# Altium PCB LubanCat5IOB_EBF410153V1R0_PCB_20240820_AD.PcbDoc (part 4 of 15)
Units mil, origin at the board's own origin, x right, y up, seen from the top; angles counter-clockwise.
Board outline 6811.02 x 4055.12 mil, 6 copper layers (TOP, GND02, ART03, ART04, PWR05, BOTTOM), stack 59.279 mil thick; 981 components, 783 nets, 3627 pads, 2669 vias.
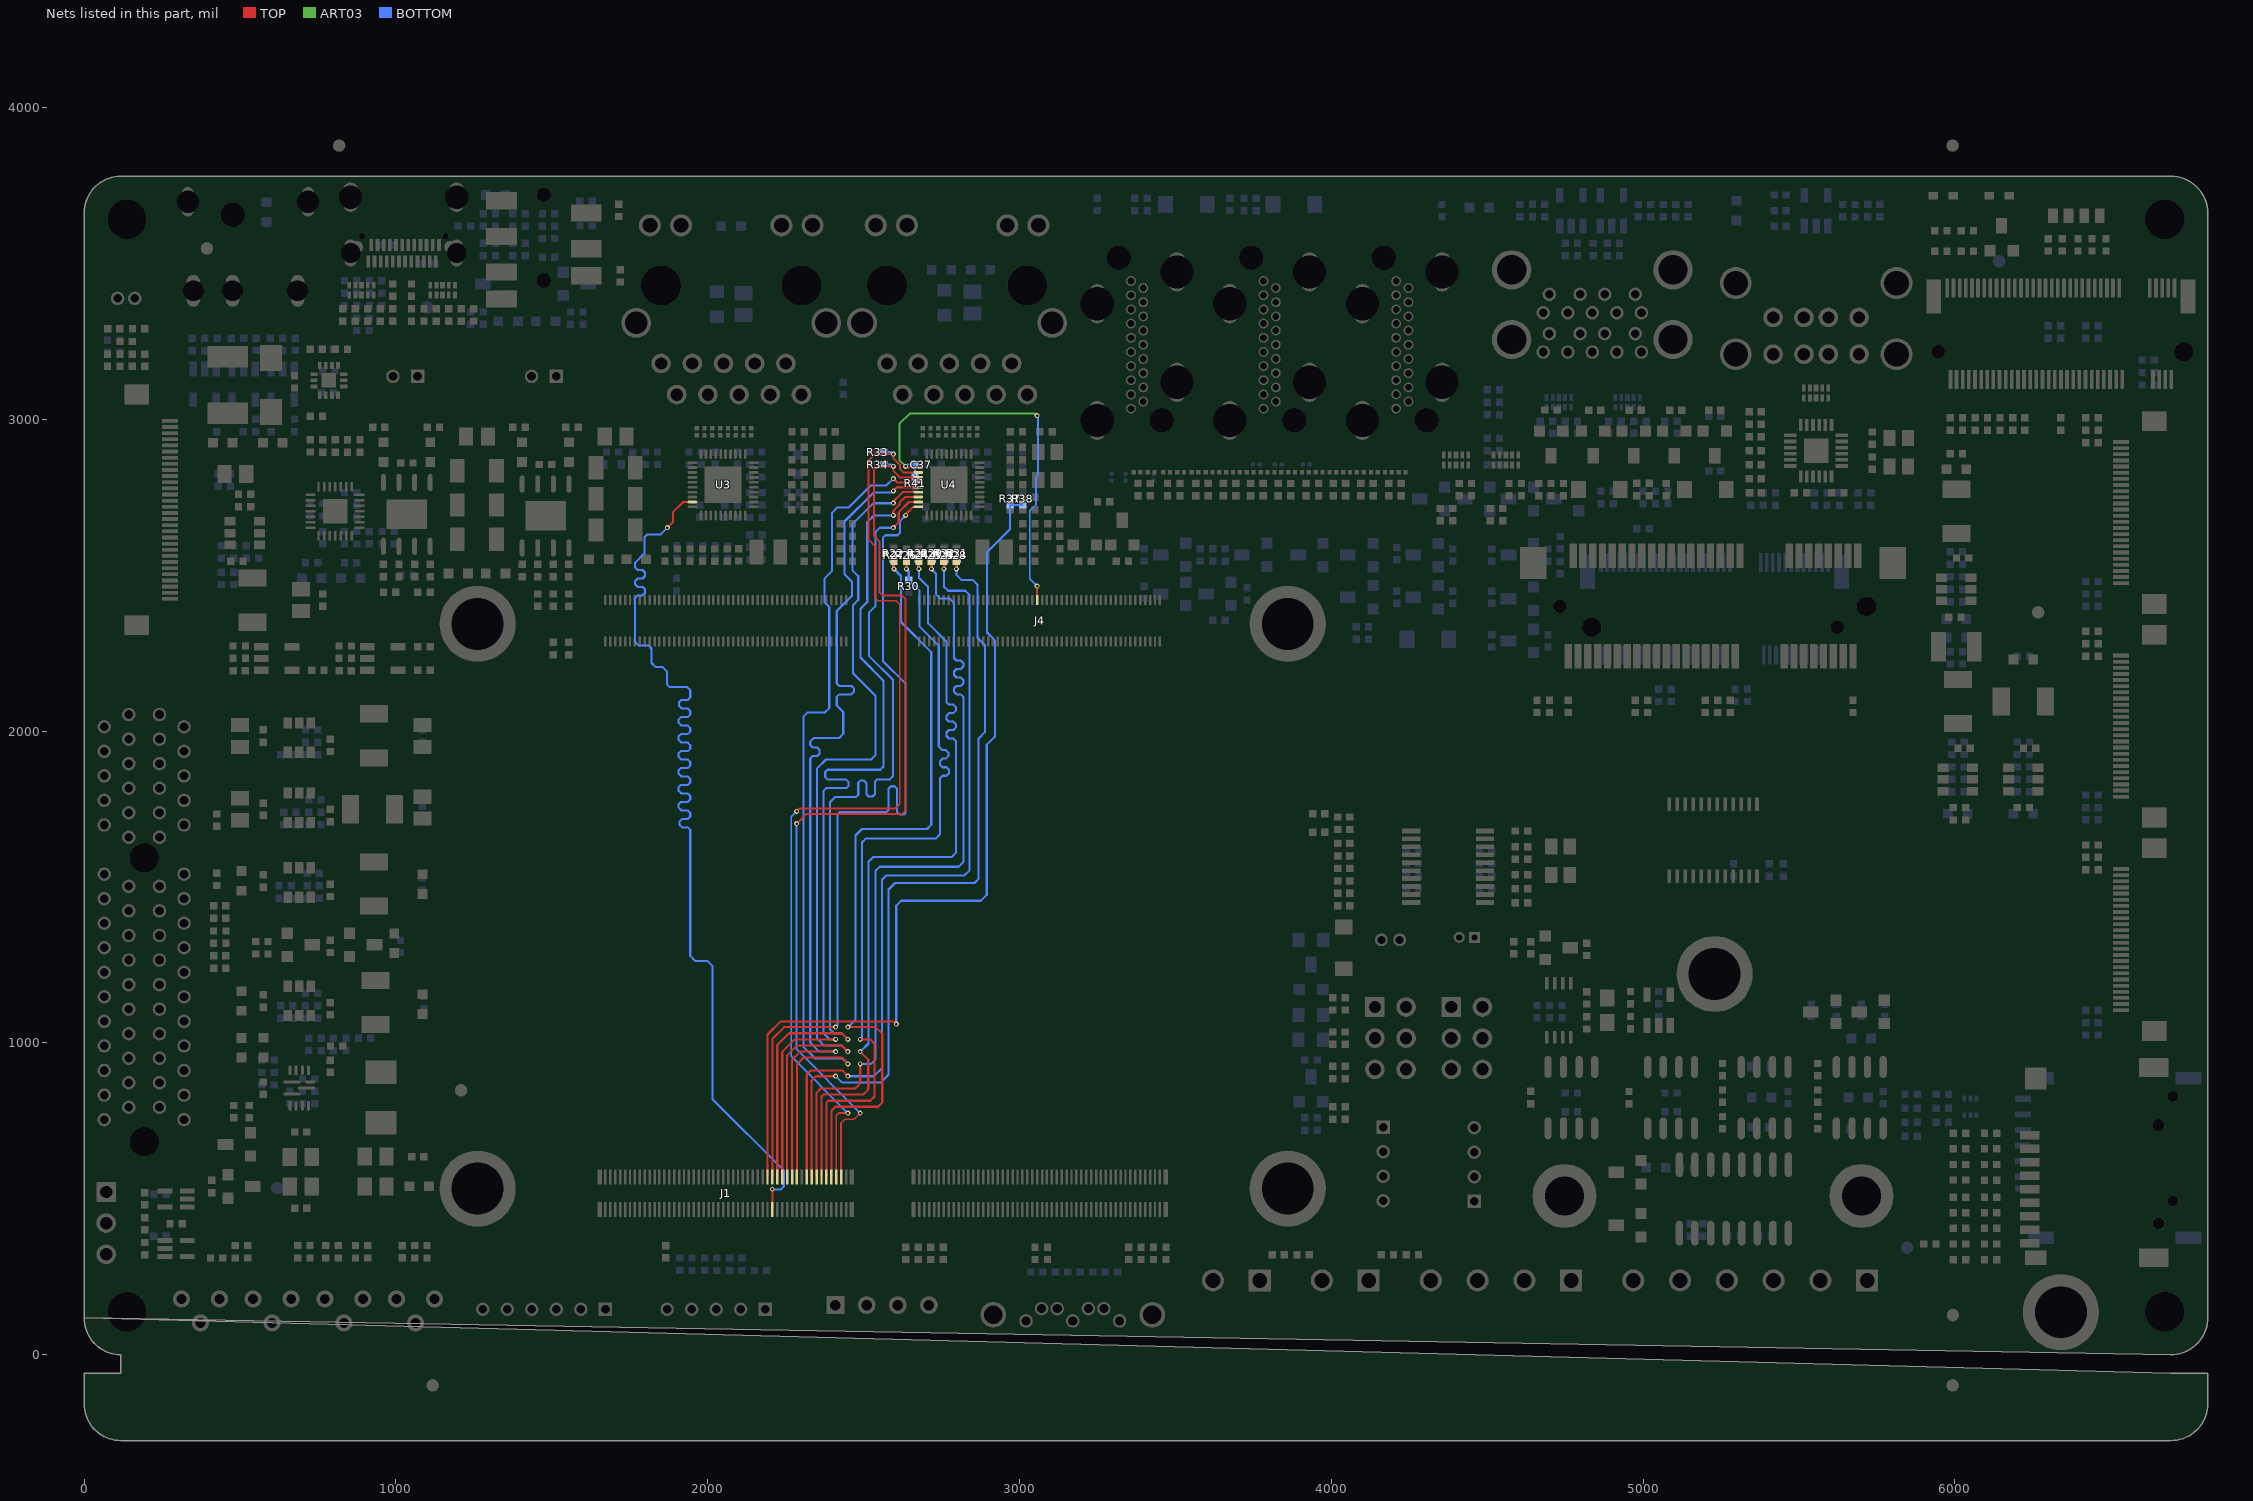
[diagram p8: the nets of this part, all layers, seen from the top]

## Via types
v1: diameter 16, hole 8, TOP to BOTTOM, 2357 vias
v2: diameter 14, hole 8, TOP to BOTTOM, 308 vias
v3: diameter 20, hole 10, TOP to BOTTOM, 4 vias

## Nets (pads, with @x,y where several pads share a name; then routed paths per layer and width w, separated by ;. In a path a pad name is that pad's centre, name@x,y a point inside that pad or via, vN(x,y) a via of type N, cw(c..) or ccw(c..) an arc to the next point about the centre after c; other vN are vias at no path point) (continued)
GMAC0_TXEN: J1.70 U3.19 | length 3227.8
  TOP w6.8: v1(1870.85,2652.2) 1888.25,2669.6 1888.25,2701.66 1921.47,2734.88 U3.19@1951.16,2734.88 ; J1.70@2207.58,465.62 v2(2207.58,530)
  BOTTOM w6.8: v1(1870.85,2652.2) 1849.51,2630.86 1807,2630.86 1797,2620.86 1797,2570 1767.39,2540.39 1767.39,2524.69 1775.35,2516.72 1791.03,2516.72 1799,2508.75 1799,2497.49 1791.03,2489.52 1775.35,2489.52 1767.39,2481.55 1767.39,2470.29 1775.35,2462.32 1791.03,2462.32 1799,2454.35 1799,2443.09 1791.03,2435.12 1775.35,2435.12 1767.39,2427.15 1767.39,2285.61 1779,2274 1811,2274 1820,2265 1820,2218.6 1833.6,2205 1855.4,2205 1869,2191.4 1869,2150 1878,2141 1935,2141 1944,2132 1944,2107.53 1936.03,2099.57 1914.97,2099.57 1908,2092.6 1908,2081.33 1916.97,2072.37 1936.03,2072.37 1944,2064.4 1944,2052.6 1936.03,2044.63 1913.97,2044.63 1907,2037.67 1907,2026.4 1915.97,2017.43 1936.03,2017.43 1944,2009.47 1944,1998.2 1936.03,1990.23 1913.97,1990.23 1907,1983.27 1907,1972 1915.97,1963.03 1936.03,1963.03 1944,1955.07 1944,1943.8 1936.03,1935.83 1913.97,1935.83 1907,1928.87 1907,1917.6 1915.97,1908.63 1936.03,1908.63 1944,1900.67 1944,1889.4 1936.03,1881.43 1913.97,1881.43 1907,1874.47 1907,1863.2 1915.97,1854.23 1936.03,1854.23 1944,1846.27 1944,1835 1936.03,1827.03 1913.97,1827.03 1907,1820.07 1907,1808.8 1915.97,1799.83 1936.03,1799.83 1944,1791.87 1944,1780.6 1936.03,1772.63 1913.97,1772.63 1907,1765.67 1907,1754.4 1915.97,1745.43 1936.03,1745.43 1944,1737.47 1944,1726.2 1936.03,1718.23 1917.97,1718.23 1910,1710.27 1910,1699 1917.97,1691.03 1936.03,1691.03 1944,1683.07 1944,1279 1961,1262 2000,1262 2015,1247 2015,820 2244,591 2244,539 2235,530 v2(2207.58,530)
GMAC1_MCLKINOUT: J1.67 R37.1 R38.1 | length 2917.8
  TOP w6.8: J1.67@2191.83,569.96 2191.83,1026.83 2234,1069 2596,1069 v1(2605,1060)
  BOTTOM w6.8: v1(2605,1060) 2605,1440 2621,1456 2876,1456 2895,1475 2895,1956 2921,1982 2921,2291 2896,2316 2896,2574 2970,2648 R37.1@2970,2725.32 R38.1@3010,2725.32
GMAC1_MDC: J1.95 R33.2 U4.13 | length 3048.4
  TOP w6: v1(2285,1742.37) 2294.63,1752 2602,1752 2616,1766 2616,2406 2604,2418 2546,2418 2537,2427 2537,2593 2516,2614 2516,2869 2535.42,2888.42 v1(2595.26,2888.42) 2595.26,2874.74 2617,2853 2617,2840 2627.63,2829.37 U4.13@2675.57,2829.37 ; J1.95@2412.3,569.96 2412.3,767.56 2419.79,775.04 v1(2450,775.04)
  BOTTOM w6: v1(2285,1742.37) 2268,1725.37 2268,957.04 v1(2450,775.04) ; R33.2@2564.68,2895 2588.68,2895 v1(2595.26,2888.42)
GMAC1_MDIO: J1.97 R34.2 U4.14 | length 3002.8
  TOP w6: v1(2285,1703) 2316,1734 2623,1734 2635,1746 2635,2423 2623,2435 2561,2435 2551,2445 2551,2609 2534,2626 2534,2842 2541.05,2849.05 v1(2595.26,2849.05) 2595.26,2834.74 2616.38,2813.62 U4.14@2675.57,2813.62 ; J1.97@2428.05,569.96 2428.05,743 2440.05,755 2469.33,755 v1(2489.37,775.04)
  BOTTOM w6: v1(2285,1703) 2285,979.41 v1(2489.37,775.04) ; R34.2@2564.68,2855 2589.31,2855 v1(2595.26,2849.05)
GMAC1_RSTN: C37.1 J4.50 R41.2 U4.12 | length 1332.7
  TOP w6: v1(2634.63,2849.05) 2638.56,2845.12 U4.12@2675.57,2845.12 ; J4.50@3056.7,2420.74 v1(3056.7,2465)
  ART03 w6: v1(2634.63,2849.05) 2615,2868.68 2615,2985 2649,3019 3050,3019 v1(3057,3012)
  BOTTOM w6: v1(2634.63,2849.05) 2640.58,2855 C37.1@2665.32,2855 2665,2854.68 R41.2@2665,2814.68 ; v1(3056.7,2465) 3033,2488.7 3033,2706 3053.01,2726.01 3053.01,2814.01 3060,2821 3060,3009 v1(3057,3012)
GMAC1_RXCLK: J1.85 R28.1 R31.1 | length 2595.6
  TOP w6.8: J1.85@2333.56,569.96 2333.56,879.55 2347.16,893.15 v1(2410.63,893.15) ; v1(2797.62,2520) R28.1@2797.62,2544.69
  BOTTOM w6.8: v1(2410.63,893.15) 2431.43,872.35 2554.35,872.35 2579.8,897.8 2579.8,1492 2600.8,1513 2856,1513 2869,1526 2869,1976 2889,1996 2889,2276 2865,2300 2865,2470 2850,2485 2813.6,2485 2797.62,2500.98 v1(2797.62,2520) 2800,2522.38 R31.1@2800,2550.32
GMAC1_RXD0: J1.87 R20.2 R23.1 | length 2586.3
  TOP w6.8: J1.87@2349.31,569.96 2349.31,840.18 2362.91,853.78 2473.78,853.78 2489.37,869.37 v1(2489.37,932.52) ; v1(2717.62,2520) R23.1@2717.62,2544.69
  BOTTOM w6.8: v1(2489.37,932.52) 2524.4,932.52 2538,946.12 2538,1551.4 2551.6,1565 2805,1565 2820,1580 2820,2109.68 2812.03,2117.65 2797.97,2117.65 2790,2125.61 2790,2136.88 2797.97,2144.85 2812.03,2144.85 2820,2152.82 2820,2164.08 2812.03,2172.05 2797.97,2172.05 2790,2180.01 2790,2191.28 2797.97,2199.25 2812.03,2199.25 2820,2207.22 2820,2218.48 2812.03,2226.45 2797.97,2226.45 2790,2234.41 2790,2411.4 2776.4,2425 2745.6,2425 2732,2438.6 2732,2505.62 v1(2717.62,2520) 2720,2522.38 R20.2@2720,2550.32
GMAC1_RXD1: J1.89 R21.2 R24.1 | length 2568.1
  TOP w6.8: J1.89@2365.06,569.96 2365.06,828.2 2371.86,835 2500,835 2515,850 2515,946.26 v1(2489.37,971.89) ; v1(2677.62,2520) R24.1@2677.62,2544.69
  BOTTOM w6.8: v1(2489.37,971.89) 2515.6,998.12 2515.6,1580.6 2531,1596 2782.4,1596 2796,1609.6 2796,1968.14 2788.03,1976.11 2773.97,1976.11 2766,1984.08 2766,1995.34 2773.97,2003.31 2788.03,2003.31 2796,2011.28 2796,2022.54 2788.03,2030.51 2773.97,2030.51 2766,2038.48 2766,2049.74 2773.97,2057.71 2788.03,2057.71 2796,2065.68 2796,2076.94 2788.03,2084.91 2773.97,2084.91 2766,2092.88 2766,2287 2707,2346 2707,2462 2677.62,2491.38 v1(2677.62,2520) 2675,2522.62 R21.2@2675,2550.32
GMAC1_RXD2: J1.91 R26.1 R30.1 | length 2511.1
  TOP w6.8: J1.91@2380.81,569.96 2380.81,807.61 2387.61,814.41 2521.4,814.41 2535,828.01 2535,997.66 2521.4,1011.26 v1(2489.37,1011.26) ; v1(2637.62,2520) R26.1@2637.62,2544.69
  BOTTOM w6.8: v1(2489.37,1011.26) 2494.8,1016.69 2494.8,1642.8 2507,1655 2731.4,1655 2745,1668.6 2745,1848.73 2752.97,1856.7 2766.03,1856.7 2774,1864.67 2774,1875.93 2766.03,1883.9 2752.97,1883.9 2745,1891.87 2745,1903.67 2752.97,1911.64 2764.03,1911.64 2772,1919.6 2772,1930.87 2764.03,1938.84 2752.97,1938.84 2741,1950.8 2741,2274 2680,2335 2680,2449.68 R30.1@2645,2484.68 2645,2512.62 v1(2637.62,2520)
GMAC1_RXD3: J1.93 R22.2 R27.1 | length 2533.7
  TOP w6.8: J1.93@2396.55,569.96 2396.55,781.4 2410.16,795 2546.4,795 2560,808.6 2560,1030 2539.37,1050.63 v1(2450,1050.63) ; v1(2597.62,2520) R27.1@2597.62,2544.69
  BOTTOM w6.8: v1(2450,1050.63) 2474,1074.63 2474,1665 2495,1686 2703.4,1686 2717,1699.6 2717,2253 2620,2350 2620,2497.62 v1(2597.62,2520) 2595,2522.62 R22.2@2595,2550.32
GMAC1_RXDV_CRS: J1.83 R29.1 R32.1 | length 2580.3
  TOP w6.8: J1.83@2317.82,569.96 2317.82,898.4 2331.41,912 2431.15,912 v1(2450,893.15) ; v1(2757.62,2520) R29.1@2757.62,2544.69
  BOTTOM w6.8: v1(2450,893.15) 2533.15,893.15 2559,919 2559,1523.4 2572.6,1537 2823,1537 2840,1554 2840,2436.4 2826.4,2450 2771.22,2450 2757.62,2463.6 v1(2757.62,2520) 2760,2522.38 R32.1@2760,2550.32
GMAC1_TXCLK: J1.69 U4.20 | length 2816.3
  TOP w6.8: J1.69@2207.58,569.96 2207.58,1012.58 2245.63,1050.63 v1(2410.63,1050.63) ; v1(2634.63,2691.57) 2634.63,2694.63 2659.13,2719.13 U4.20@2675.57,2719.13
  BOTTOM w6.8: v1(2410.63,1050.63) 2416,1056 2416,1733.2 2422.8,1740 2573.23,1740 2580.03,1746.8 2580.03,1815.03 2588,1823 2599.27,1823 2607.23,1815.03 2607.23,1740.97 2616.2,1732 2628,1732 2635,1739 2635,2152 2562,2225 2562,2620 2570,2628 2609,2628 2617.23,2636.23 2617.23,2674.17 v1(2634.63,2691.57)
GMAC1_TXD0: J1.73 U4.18 | length 2837.6
  TOP w6.8: J1.73@2239.07,569.96 2239.07,971.07 2279.26,1011.26 v1(2410.63,1011.26) ; v1(2595.26,2691.57) 2595.26,2706.26 2615,2726 2615,2732 2633.63,2750.63 U4.18@2675.57,2750.63
  BOTTOM w6.8: v1(2410.63,1011.26) 2390.74,1011.26 2372,1030 2372,1809.07 2379.97,1817.03 2444.03,1817.03 2452,1825 2452,1836.27 2444.03,1844.23 2384.97,1844.23 2377,1852.2 2377,1869 2384,1876 2553.4,1876 2564,1886.6 2564,2162 2490,2236 2490,2392 2512,2414 2512,2670 2533.57,2691.57 v1(2595.26,2691.57)
GMAC1_TXD1: J1.75 U4.17 | length 2836.2
  TOP w6.8: J1.75@2254.82,569.96 2254.82,959.82 2286,991 2430.89,991 v1(2450,971.89) ; v1(2595.26,2730.94) 2595.26,2736.26 2625.38,2766.38 U4.17@2675.57,2766.38
  BOTTOM w6.8: v1(2450,971.89) 2430.89,991 2374,991 2351,1014 2351,1880.4 2379.6,1909 2524.4,1909 2538,1922.6 2538,2114 2466,2186 2466,2404 2483,2421 2483,2497 2464,2516 2464,2663.61 2531.33,2730.94 v1(2595.26,2730.94)
GMAC1_TXD2: J1.77 U4.16 | length 2836.6
  TOP w6.8: J1.77@2270.57,569.96 2270.57,945.57 2296.89,971.89 v1(2410.63,971.89) ; v1(2595.26,2770.31) 2607.08,2782.13 U4.16@2675.57,2782.13
  BOTTOM w6.8: v1(2410.63,971.89) 2358.11,971.89 2329,1001 2329,1912.07 2336.97,1920.03 2351.03,1920.03 2359,1928 2359,1939.27 2351.03,1947.23 2336.97,1947.23 2329,1955.2 2329,1967 2339.4,1977.4 2421.4,1977.4 2435,1991 2435,2061 2414,2082 2414,2109.67 2421.97,2117.64 2461.1,2117.64 2469.07,2125.61 2469.07,2136.87 2461.1,2144.84 2421.97,2144.84 2414,2152.81 2414,2385 2462.4,2433.4 2462.4,2479.6 2439,2503 2439,2672 2532.2,2765.2 2590.15,2765.2 v1(2595.26,2770.31)
GMAC1_TXD3: J1.79 U4.15 | length 2830.6
  TOP w6.8: J1.79@2286.32,569.96 2286.32,931.32 2308,953 2429.52,953 v1(2450,932.52) ; v1(2595.26,2809.68) 2607.07,2797.87 U4.15@2675.57,2797.87
  BOTTOM w6.8: v1(2450,932.52) 2432.52,950 2345,950 2307,988 2307,2046.4 2320.6,2060 2376.4,2060 2390,2073.6 2390,2398 2375,2413 2375,2490 2399,2514 2399,2700 2416,2717 2453,2717 2524,2788 2573.58,2788 v1(2595.26,2809.68)
GMAC1_TXEN: J1.71 U4.19 | length 2837.9
  TOP w6.8: J1.71@2223.33,569.96 2223.33,993.33 2261,1031 2430.26,1031 v1(2450,1011.26) ; v1(2595.26,2652.2) 2612.66,2669.6 2612.66,2701.66 2645.88,2734.88 U4.19@2675.57,2734.88
  BOTTOM w6.8: v1(2450,1011.26) 2430.26,1031 2405.6,1031 2392,1044.6 2392,1771 2410,1789 2476.2,1789 2483,1795.8 2483,1834.2 2489.8,1841 2501.6,1841 2509.57,1833.03 2509.57,1797.97 2517.53,1790 2528.8,1790 2536.77,1797.97 2536.77,1837.03 2544.73,1845 2584,1845 2595,1856 2595,2164 2517,2242 2517,2379 2538,2400 2538,2638 2552.2,2652.2 v1(2595.26,2652.2)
